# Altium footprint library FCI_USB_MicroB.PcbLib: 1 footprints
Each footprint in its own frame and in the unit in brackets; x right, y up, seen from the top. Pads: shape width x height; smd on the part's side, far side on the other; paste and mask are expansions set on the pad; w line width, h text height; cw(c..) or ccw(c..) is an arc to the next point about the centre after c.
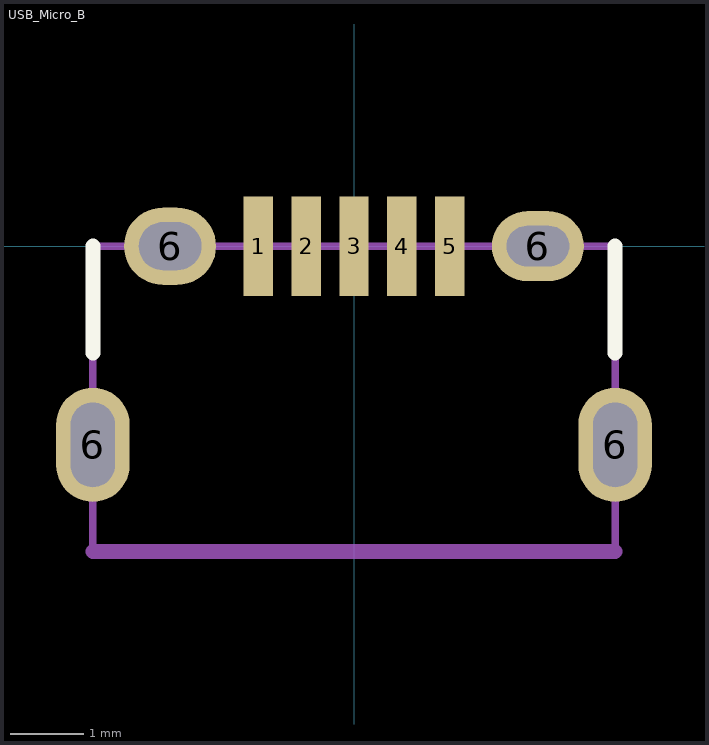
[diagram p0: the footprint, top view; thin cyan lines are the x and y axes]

## USB_Micro_B [mm] "FCI USB Micro B Connector"
pads (9):
  rect 0.4x1.35 smd: 1(-1.3,0) 2(-0.65,0) 3(0,0) 4(0.65,0) 5(1.3,0)
  oval 1x1.55 hole 0.6 slot 1.15 at 90 deg: 6(-3.55,-2.7) 6(3.55,-2.7)
  oval 1.25x1.05 hole 0.65 slot 0.85 at 0 deg: 6(-2.5,0)
  oval 1.25x0.95 hole 0.55 slot 0.85 at 0 deg: 6(2.5,0)
Top Overlay:
  lines w0.203: -3.55,-1.45 -3.55,0 ; 3.55,-1.45 3.55,0
Mechanical 1:
  lines w0.203: -3.55,-4.15 3.55,-4.15
Mechanical 31:
  lines w0.102: -3.55,-4.15 3.55,-4.15 3.55,0 -3.55,0 -3.55,-4.15
  text ".Comment" at 2.5,-1.25 h0.76
  text ".Designator" at 2.475,-2.6 h0.76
